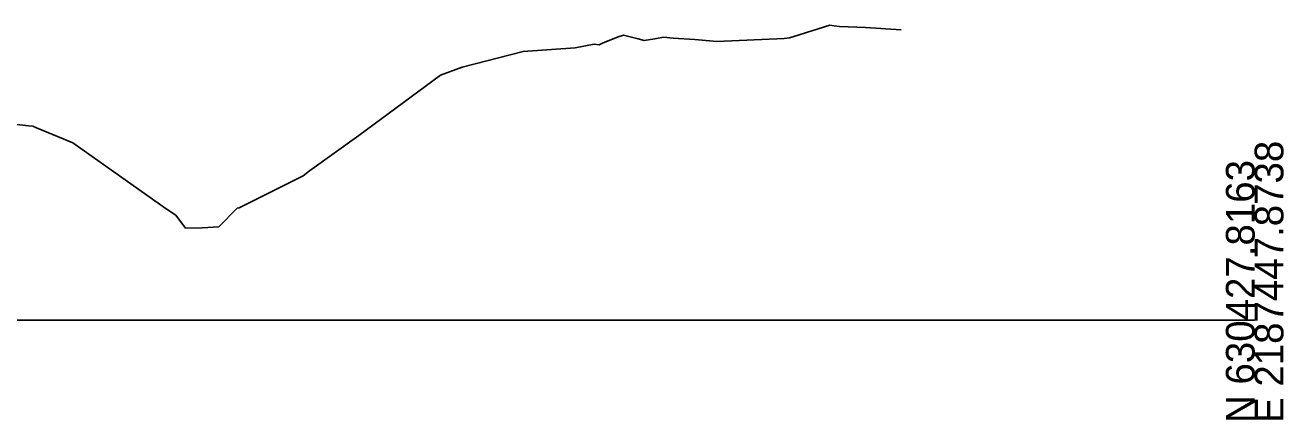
# Model space of a CAD drawing. Extents: x -26 to 4903, y -1010 to 9587.
# Drawn here: x 180.3 to 302.8, y 4490.3 to 4528.7 of the extents above; entities that cross this region are included whole.
import ezdxf

# ---------------------------------------------------------------- set-up
doc = ezdxf.new("R2010")
doc.units = 0
doc.layers.add('Exist Cross Section Cell', color=7, linetype='Continuous')
doc.layers.add('Exist XS Ground Line', color=7, linetype='Continuous')

msp = doc.modelspace()

# ---------------------------------------------------------------- linework, layer by layer
at = {"layer": 'Exist Cross Section Cell'}
msp.add_line((150, 4500), (300, 4500), dxfattribs=at)
at = {"layer": 'Exist XS Ground Line'}
for p, q in [((255.12, 4527.63), (258.64, 4528.74)), ((258.64, 4528.74), (259.06, 4528.69)), ((259.06, 4528.69), (259.58, 4528.62)), ((259.58, 4528.62), (262.11, 4528.5)), ((262.11, 4528.5), (265.59, 4528.29)), ((236.5, 4526.99), (238.03, 4527.6)), ((238.03, 4527.6), (238.54, 4527.76)), ((238.54, 4527.76), (239.97, 4527.41)), ((239.97, 4527.41), (240.54, 4527.26)), ((240.54, 4527.26), (241.59, 4527.42)), ((241.59, 4527.42), (242.44, 4527.56)), ((242.44, 4527.56), (243.38, 4527.47)), ((243.38, 4527.47), (245.5, 4527.33)), ((245.5, 4527.33), (247.62, 4527.15)), ((247.62, 4527.15), (254.18, 4527.45)), ((254.18, 4527.45), (254.72, 4527.5)), ((254.72, 4527.5), (255.12, 4527.63)), ((222.82, 4524.65), (228.77, 4526.17)), ((228.77, 4526.17), (233.83, 4526.54)), ((233.83, 4526.54), (235.68, 4526.89)), ((235.68, 4526.89), (236.18, 4526.82)), ((236.18, 4526.82), (236.5, 4526.99)), ((212.78, 4517.99), (220.74, 4523.88)), ((220.74, 4523.88), (222.82, 4524.65)), ((171.72, 4519.99), (180.6, 4518.94)), ((180.6, 4518.94), (181.02, 4518.89)), ((181.02, 4518.89), (181.39, 4518.73)), ((181.39, 4518.73), (184.91, 4517.29)), ((207.97, 4514.54), (212.78, 4517.99)), ((184.91, 4517.29), (194.01, 4510.86)), ((201.13, 4510.95), (207.36, 4514.08)), ((207.36, 4514.08), (207.97, 4514.54)), ((194.01, 4510.86), (194.95, 4510.24)), ((194.95, 4510.24), (195.89, 4508.96)), ((199.15, 4509.1), (200.92, 4510.91)), ((200.92, 4510.91), (201.13, 4510.95)), ((195.89, 4508.96), (197.52, 4509.01)), ((197.52, 4509.01), (199.15, 4509.1))]:
    msp.add_line(p, q, dxfattribs=at)

# ---------------------------------------------------------------- texts
at = {"layer": 'Exist Cross Section Cell'}
for s, p in [('E 2187447.8738', (302.8, 4490)), ('N 630427.8163', (300, 4490))]:
    msp.add_text(s, height=2.8, rotation=90, dxfattribs=at).set_placement(p)

doc.saveas('drawing.dxf')
